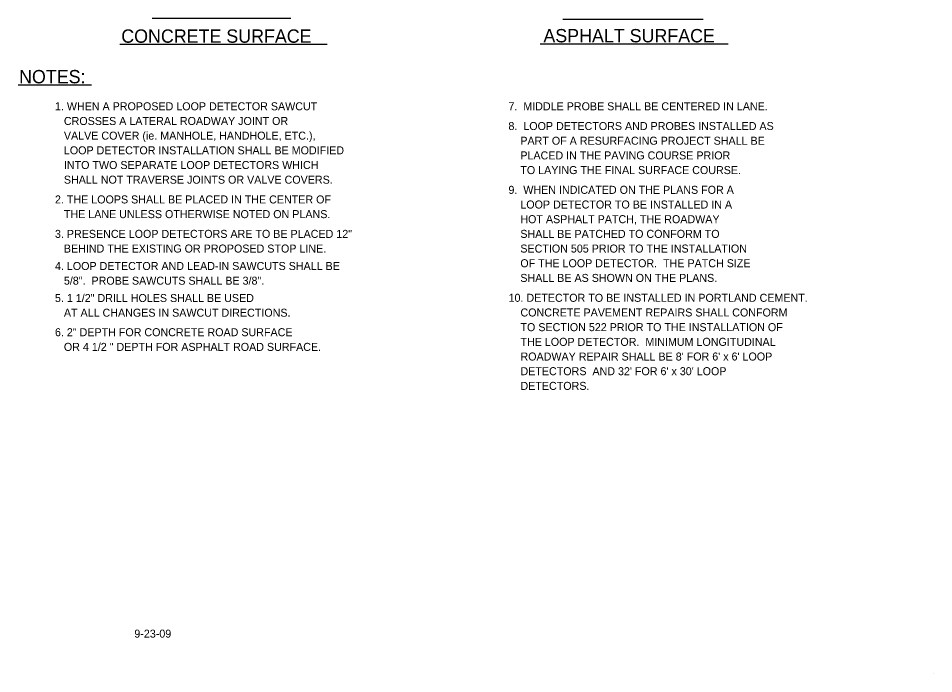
# Model space of a CAD drawing. Extents: x -1550.42 to -1543.2, y 2481.09 to 2491.
# Drawn here: x -1550.06 to -1543.2, y 2481.09 to 2486 of the extents above; entities that cross this region are included whole.
import ezdxf

# ---------------------------------------------------------------- set-up
doc = ezdxf.new("R2010")
doc.units = 0
for name, color, linetype in [('DETL-NOTE', 7, 'Continuous'), ('DETL-TITL', 7, 'Continuous'), ('TTLB-TEXT', 7, 'Continuous')]:
    doc.layers.add(name, color=color, linetype=linetype)

msp = doc.modelspace()

# ---------------------------------------------------------------- linework, layer by layer
at = {"layer": 'DETL-NOTE'}
msp.add_line((-1550.0578, 2485.503), (-1549.5085, 2485.503), dxfattribs=at)
at = {"layer": 'DETL-TITL'}
for p, q in [((-1549.0546, 2486.0022), (-1548.0144, 2486.0022)), ((-1545.9756, 2485.9969), (-1544.9248, 2485.9969)), ((-1549.2973, 2485.8075), (-1547.7424, 2485.8075)), ((-1546.1462, 2485.8101), (-1544.7381, 2485.8101))]:
    msp.add_line(p, q, dxfattribs=at)
at = {"layer": 'TTLB-TEXT'}
msp.add_line((-1543.1965, 2481.0915), (-1543.1965, 2481.0915), dxfattribs=at)
msp.add_line((-1543.1965, 2481.0915), (-1543.1965, 2481.0915), dxfattribs=at)

# ---------------------------------------------------------------- texts
at = {"layer": 'DETL-NOTE'}
for s, height, p in [('NOTES:', 0.1, (-1550.052, 2485.515)), ('1. WHEN A PROPOSED LOOP DETECTOR SAWCUT', 0.06, (-1549.783, 2485.313)), ('7.  MIDDLE PROBE SHALL BE CENTERED IN LANE.', 0.06, (-1546.384, 2485.313)), ('   CROSSES A LATERAL ROADWAY JOINT OR', 0.06, (-1549.783, 2485.203)), ('8.  LOOP DETECTORS AND PROBES INSTALLED AS', 0.06, (-1546.384, 2485.165)), ('   VALVE COVER (ie. MANHOLE, HANDHOLE, ETC.),', 0.06, (-1549.783, 2485.093)), ('    PART OF A RESURFACING PROJECT SHALL BE', 0.06, (-1546.384, 2485.055)), ('   LOOP DETECTOR INSTALLATION SHALL BE MODIFIED', 0.06, (-1549.783, 2484.983)), ('    PLACED IN THE PAVING COURSE PRIOR', 0.06, (-1546.384, 2484.945)), ('   INTO TWO SEPARATE LOOP DETECTORS WHICH', 0.06, (-1549.783, 2484.873)), ('    TO LAYING THE FINAL SURFACE COURSE.', 0.06, (-1546.384, 2484.835)), ('   SHALL NOT TRAVERSE JOINTS OR VALVE COVERS.', 0.06, (-1549.783, 2484.763)), ('9.  WHEN INDICATED ON THE PLANS FOR A', 0.06, (-1546.384, 2484.687)), ('2. THE LOOPS SHALL BE PLACED IN THE CENTER OF', 0.06, (-1549.783, 2484.615)), ('    LOOP DETECTOR TO BE INSTALLED IN A', 0.06, (-1546.384, 2484.577)), ('   THE LANE UNLESS OTHERWISE NOTED ON PLANS.', 0.06, (-1549.783, 2484.505)), ('    HOT ASPHALT PATCH, THE ROADWAY', 0.06, (-1546.384, 2484.467)), ('3. PRESENCE LOOP DETECTORS ARE TO BE PLACED 12"', 0.06, (-1549.783, 2484.357)), ('    SHALL BE PATCHED TO CONFORM TO', 0.06, (-1546.384, 2484.357)), ('   BEHIND THE EXISTING OR PROPOSED STOP LINE.', 0.06, (-1549.783, 2484.247)), ('    SECTION 505 PRIOR TO THE INSTALLATION', 0.06, (-1546.384, 2484.247)), ('    OF THE LOOP DETECTOR.  THE PATCH SIZE', 0.06, (-1546.384, 2484.137)), ('4. LOOP DETECTOR AND LEAD-IN SAWCUTS SHALL BE ', 0.06, (-1549.783, 2484.1163)), ('   5/8".  PROBE SAWCUTS SHALL BE 3/8". ', 0.06, (-1549.783, 2484.0063)), ('    SHALL BE AS SHOWN ON THE PLANS.', 0.06, (-1546.384, 2484.027)), ('5. 1 1/2" DRILL HOLES SHALL BE USED', 0.06, (-1549.783, 2483.8763)), ('10. DETECTOR TO BE INSTALLED IN PORTLAND CEMENT.', 0.06, (-1546.383, 2483.878)), ('   AT ALL CHANGES IN SAWCUT DIRECTIONS.', 0.06, (-1549.783, 2483.7663)), ('    CONCRETE PAVEMENT REPAIRS SHALL CONFORM ', 0.06, (-1546.383, 2483.768)), ('    TO SECTION 522 PRIOR TO THE INSTALLATION OF', 0.06, (-1546.383, 2483.658)), ('6. 2" DEPTH FOR CONCRETE ROAD SURFACE', 0.06, (-1549.783, 2483.6201)), ('    THE LOOP DETECTOR.  MINIMUM LONGITUDINAL', 0.06, (-1546.383, 2483.548)), ('   OR 4 1/2 " DEPTH FOR ASPHALT ROAD SURFACE.', 0.06, (-1549.783, 2483.5101)), ("    ROADWAY REPAIR SHALL BE 8' FOR 6' x 6' LOOP", 0.06, (-1546.383, 2483.438)), ("    DETECTORS  AND 32' FOR 6' x 30' LOOP", 0.06, (-1546.383, 2483.328)), ('    DETECTORS.', 0.06, (-1546.383, 2483.218))]:
    msp.add_text(s, height=height, dxfattribs=at).set_placement(p)
at = {"layer": 'DETL-TITL'}
for s, p in [('CONCRETE SURFACE', (-1549.286, 2485.819)), ('ASPHALT SURFACE', (-1546.122, 2485.822))]:
    msp.add_text(s, height=0.100002, dxfattribs=at).set_placement(p)
at = {"layer": 'TTLB-TEXT'}
msp.add_text('9-23-09', height=0.06, dxfattribs=at).set_placement((-1549.188, 2481.3615))

doc.saveas('drawing.dxf')
